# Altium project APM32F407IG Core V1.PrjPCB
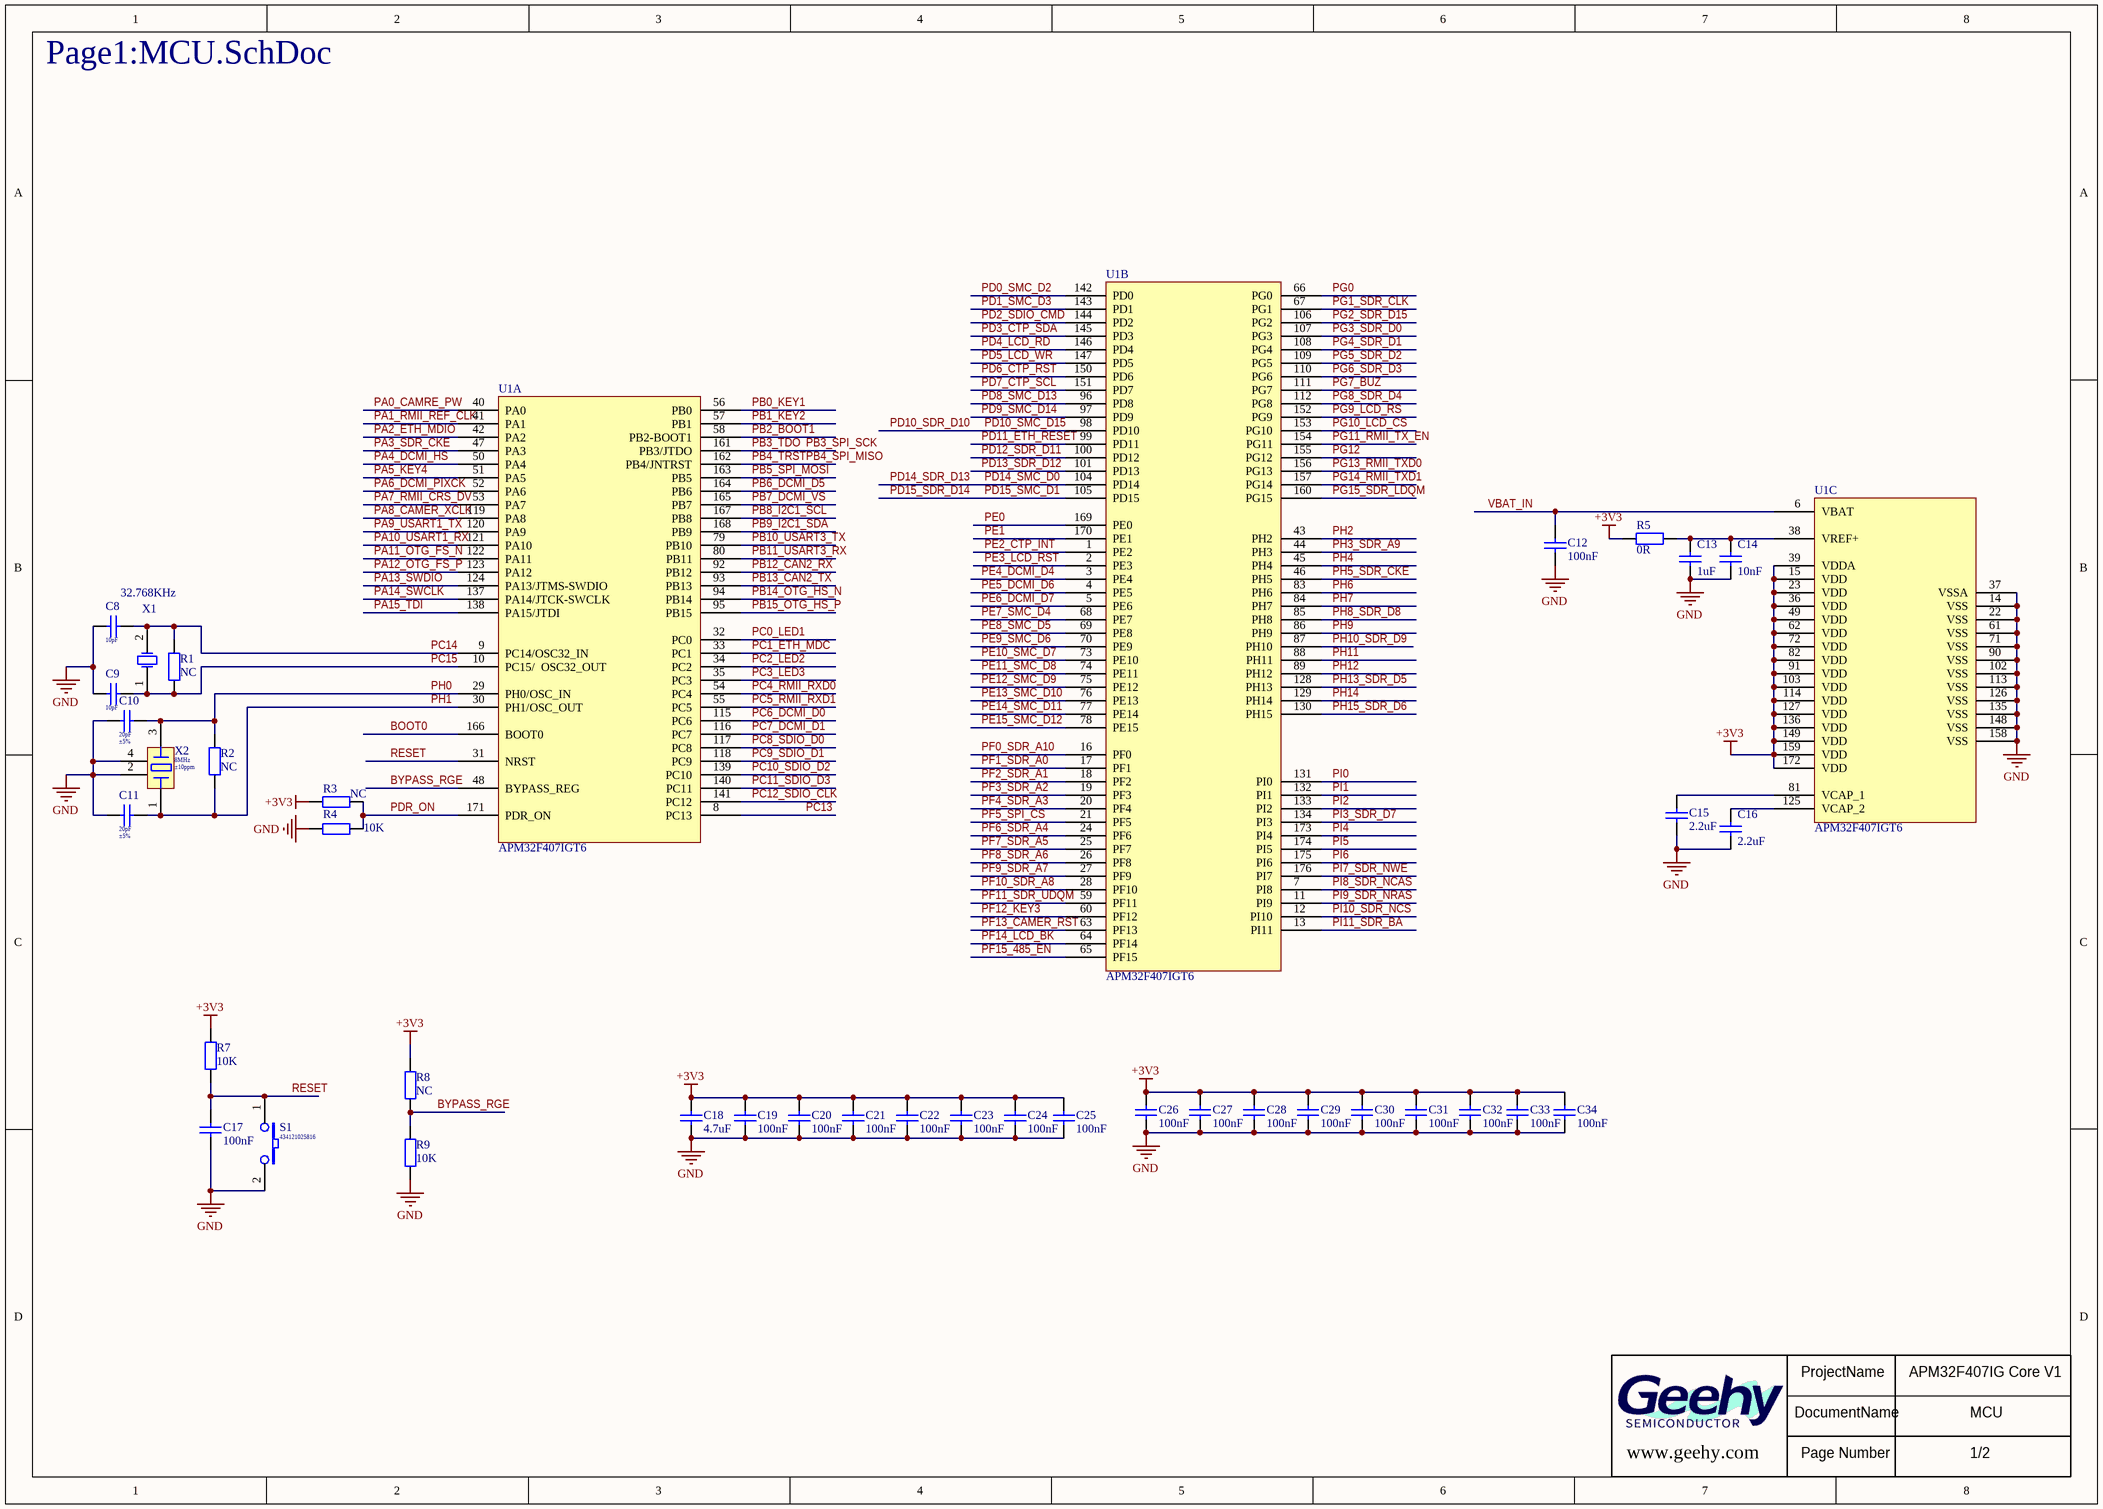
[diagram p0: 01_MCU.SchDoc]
2 sheets, 55 parts. Net scope: global (net labels, ports and power ports of the same name join across sheets).
Board file: APM32F407IG Core V1.PcbDoc
Sheets:
  01_MCU.SchDoc
  02_Connect.SchDoc

## Sheet 01_MCU.SchDoc
size A3

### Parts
C8  10pF  [C0603]
C9  10pF  [C0603]
C10  Tolerance: ±5%  [C0603]  (hidden comment: 20pF)
C11  Tolerance: ±5%  [C0603]  (hidden comment: 20pF)
C12  100nF  [C0603]
C13  1uF  [C0603]
C14  10nF  [C0603]
C15  2.2uF  [C0603]
C16  2.2uF  [C0603]
C17  100nF  [C0603]
C18  4.7uF  [C0805]
C19  100nF  [C0603]
C20  100nF  [C0603]
C21  100nF  [C0603]
C22  100nF  [C0603]
C23  100nF  [C0603]
C24  100nF  [C0603]
C25  100nF  [C0603]
C26  100nF  [C0603]
C27  100nF  [C0603]
C28  100nF  [C0603]
C29  100nF  [C0603]
C30  100nF  [C0603]
C31  100nF  [C0603]
C32  100nF  [C0603]
C33  100nF  [C0603]
C34  100nF  [C0603]
R1  NC  [R0603]
R2  NC  [R0603]
R3  NC  [R0603]
R4  10K  [R0603]
R5  0R  [R0603]
R7  10K  [R0603]
R8  NC  [R0603]
R9  10K  [R0603]
S1  434121025816  [SW-SMD-6X3R8X2R5-1]
U1  APM32F407IGT6  [LQFP-176N]  (parts A,B,C of 3)
X1  32.768KHz  [R1206]
X2  Tolerance: ±10ppm  [XTAL3225]  (hidden comment: 8MHz)

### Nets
+3V3: C18.1 C19.1 C20.1 C21.1 C22.1 C23.1 C24.1 C25.1 C26.1 C27.1 C28.1 C29.1 C30.1 C31.1 C32.1 C33.1 C34.1 R3.2 R5.1 R7.2 R8.2 U1.15(VDD) U1.23(VDD) U1.36(VDD) U1.39(VDDA) U1.49(VDD) U1.62(VDD) U1.72(VDD) U1.82(VDD) U1.91(VDD) U1.103(VDD) U1.114(VDD) U1.127(VDD) U1.136(VDD) U1.149(VDD) U1.159(VDD) U1.172(VDD)
GND: C8.2 C9.2 C10.2 C11.2 C12.2 C13.2 C14.2 C15.2 C16.2 C17.2 C18.2 C19.2 C20.2 C21.2 C22.2 C23.2 C24.2 C25.2 C26.2 C27.2 C28.2 C29.2 C30.2 C31.2 C32.2 C33.2 C34.2 R4.1 R9.1 S1.2 U1.14(VSS) U1.22(VSS) U1.37(VSSA) U1.61(VSS) U1.71(VSS) U1.90(VSS) U1.102(VSS) U1.113(VSS) U1.126(VSS) U1.135(VSS) U1.148(VSS) U1.158(VSS) X2.2(GND) X2.4(GND)
BOOT0: U1.166(BOOT0)
BYPASS_RGE: R8.1 R9.2 U1.48(BYPASS_REG)
PA0_CAMRE_PW: U1.40(PA0)
PA1_RMII_REF_CLK: U1.41(PA1)
PA2_ETH_MDIO: U1.42(PA2)
PA3_SDR_CKE: U1.47(PA3)
PA4_DCMI_HS: U1.50(PA4)
PA5_KEY4: U1.51(PA5)
PA6_DCMI_PIXCK: U1.52(PA6)
PA7_RMII_CRS_DV: U1.53(PA7)
PA8_CAMER_XCLK: U1.119(PA8)
PA9_USART1_TX: U1.120(PA9)
PA10_USART1_RX: U1.121(PA10)
PA11_OTG_FS_N: U1.122(PA11)
PA12_OTG_FS_P: U1.123(PA12)
PA13_SWDIO: U1.124(PA13/JTMS-SWDIO)
PA14_SWCLK: U1.137(PA14/JTCK-SWCLK)
PA15_TDI: U1.138(PA15/JTDI)
PB0_KEY1: U1.56(PB0)
PB1_KEY2: U1.57(PB1)
PB2_BOOT1: U1.58(PB2-BOOT1)
PB3_SPI_SCK: U1.161(PB3/JTDO)  [also labelled PB3_TDO]
PB4_SPI_MISO: U1.162(PB4/JNTRST)  [also labelled PB4_TRST]
PB5_SPI_MOSI: U1.163(PB5)
PB6_DCMI_D5: U1.164(PB6)
PB7_DCMI_VS: U1.165(PB7)
PB8_I2C1_SCL: U1.167(PB8)
PB9_I2C1_SDA: U1.168(PB9)
PB10_USART3_TX: U1.79(PB10)
PB11_USART3_RX: U1.80(PB11)
PB12_CAN2_RX: U1.92(PB12)
PB13_CAN2_TX: U1.93(PB13)
PB14_OTG_HS_N: U1.94(PB14)
PB15_OTG_HS_P: U1.95(PB15)
PC0_LED1: U1.32(PC0)
PC1_ETH_MDC: U1.33(PC1)
PC2_LED2: U1.34(PC2)
PC3_LED3: U1.35(PC3)
PC4_RMII_RXD0: U1.54(PC4)
PC5_RMII_RXD1: U1.55(PC5)
PC6_DCMI_D0: U1.115(PC6)
PC7_DCMI_D1: U1.116(PC7)
PC8_SDIO_D0: U1.117(PC8)
PC9_SDIO_D1: U1.118(PC9)
PC10_SDIO_D2: U1.139(PC10)
PC11_SDIO_D3: U1.140(PC11)
PC12_SDIO_CLK: U1.141(PC12)
PC13: U1.8(PC13)
PC14: C8.1 R1.2 U1.9(PC14/OSC32_IN) X1.2(OSC2)
PC15: C9.1 R1.1 U1.10(PC15/__OSC32_OUT) X1.1(OSC1)
PD0_SMC_D2: U1.142(PD0)
PD1_SMC_D3: U1.143(PD1)
PD2_SDIO_CMD: U1.144(PD2)
PD3_CTP_SDA: U1.145(PD3)
PD4_LCD_RD: U1.146(PD4)
PD5_LCD_WR: U1.147(PD5)
PD6_CTP_RST: U1.150(PD6)
PD7_CTP_SCL: U1.151(PD7)
PD8_SMC_D13: U1.96(PD8)
PD9_SMC_D14: U1.97(PD9)
PD10_SDR_D10: U1.98(PD10)  [also labelled PD10_SMC_D15]
PD11_ETH_RESET: U1.99(PD11)
PD12_SDR_D11: U1.100(PD12)
PD13_SDR_D12: U1.101(PD13)
PD14_SDR_D13: U1.104(PD14)  [also labelled PD14_SMC_D0]
PD15_SDR_D14: U1.105(PD15)  [also labelled PD15_SMC_D1]
PDR_ON: R3.1 R4.2 U1.171(PDR_ON)
PE0: U1.169(PE0)
PE1: U1.170(PE1)
PE2_CTP_INT: U1.1(PE2)
PE3_LCD_RST: U1.2(PE3)
PE4_DCMI_D4: U1.3(PE4)
PE5_DCMI_D6: U1.4(PE5)
PE6_DCMI_D7: U1.5(PE6)
PE7_SMC_D4: U1.68(PE7)
PE8_SMC_D5: U1.69(PE8)
PE9_SMC_D6: U1.70(PE9)
PE10_SMC_D7: U1.73(PE10)
PE11_SMC_D8: U1.74(PE11)
PE12_SMC_D9: U1.75(PE12)
PE13_SMC_D10: U1.76(PE13)
PE14_SMC_D11: U1.77(PE14)
PE15_SMC_D12: U1.78(PE15)
PF0_SDR_A10: U1.16(PF0)
PF1_SDR_A0: U1.17(PF1)
PF2_SDR_A1: U1.18(PF2)
PF3_SDR_A2: U1.19(PF3)
PF4_SDR_A3: U1.20(PF4)
PF5_SPI_CS: U1.21(PF5)
PF6_SDR_A4: U1.24(PF6)
PF7_SDR_A5: U1.25(PF7)
PF8_SDR_A6: U1.26(PF8)
PF9_SDR_A7: U1.27(PF9)
PF10_SDR_A8: U1.28(PF10)
PF11_SDR_UDQM: U1.59(PF11)
PF12_KEY3: U1.60(PF12)
PF13_CAMER_RST: U1.63(PF13)
PF14_LCD_BK: U1.64(PF14)
PF15_485_EN: U1.65(PF15)
PG0: U1.66(PG0)
PG1_SDR_CLK: U1.67(PG1)
PG2_SDR_D15: U1.106(PG2)
PG3_SDR_D0: U1.107(PG3)
PG4_SDR_D1: U1.108(PG4)
PG5_SDR_D2: U1.109(PG5)
PG6_SDR_D3: U1.110(PG6)
PG7_BUZ: U1.111(PG7)
PG8_SDR_D4: U1.112(PG8)
PG9_LCD_RS: U1.152(PG9)
PG10_LCD_CS: U1.153(PG10)
PG11_RMII_TX_EN: U1.154(PG11)
PG12: U1.155(PG12)
PG13_RMII_TXD0: U1.156(PG13)
PG14_RMII_TXD1: U1.157(PG14)
PG15_SDR_LDQM: U1.160(PG15)
PH0: C10.1 R2.2 U1.29(PH0/OSC_IN) X2.3
PH1: C11.1 R2.1 U1.30(PH1/OSC_OUT) X2.1
PH2: U1.43(PH2)
PH3_SDR_A9: U1.44(PH3)
PH4: U1.45(PH4)
PH5_SDR_CKE: U1.46(PH5)
PH6: U1.83(PH6)
PH7: U1.84(PH7)
PH8_SDR_D8: U1.85(PH8)
PH9: U1.86(PH9)
PH10_SDR_D9: U1.87(PH10)
PH11: U1.88(PH11)
PH12: U1.89(PH12)
PH13_SDR_D5: U1.128(PH13)
PH14: U1.129(PH14)
PH15_SDR_D6: U1.130(PH15)
PI0: U1.131(PI0)
PI1: U1.132(PI1)
PI2: U1.133(PI2)
PI3_SDR_D7: U1.134(PI3)
PI4: U1.173(PI4)
PI5: U1.174(PI5)
PI6: U1.175(PI6)
PI7_SDR_NWE: U1.176(PI7)
PI8_SDR_NCAS: U1.7(PI8)
PI9_SDR_NRAS: U1.11(PI9)
PI10_SDR_NCS: U1.12(PI10)
PI11_SDR_BA: U1.13(PI11)
RESET: C17.1 R7.1 S1.1 U1.31(NRST)
VBAT_IN: C12.1 U1.6(VBAT)
NetC13_1: C13.1 C14.1 R5.2 U1.38(VREF+)
NetC15_1: C15.1 U1.81(VCAP_1)
NetC16_1: C16.1 U1.125(VCAP_2)

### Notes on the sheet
- Page1:MCU.SchDoc
- ProjectName
- APM32F407IG Core V1
- www.geehy.com
- DocumentName
- Page Number
- 1/2
- MCU

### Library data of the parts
C8 C9 = 101CC-00365BE.01: SMD,电容量10pF,额定电压50V,偏差±1pF,材质C0G,0603; Allow Altenative Part: Y; Tolerance: ±1pF; Rated Voltage: 50V; Temperature Coefficient: C0G; serial number: 13; Categories: 电容; COMPONENTLINK 1 DESCRIPTION: GetDatasheet; Modify time: 2015年07月10号; Approved: YES
C10 C11 = 101CC-00471BW.01: 安装方式SMD,电容量20pF,额定电压50V,偏差±5%,材质NPO,0603; Allow Altenative Part: Y; Rated Voltage: 50V; Temperature Coefficient: NP0; serial number: 38; Categories: 电容; COMPONENTLINK 1 DESCRIPTION: GetDatasheet; Modify time: 2016年08月22号; Approved: YES
C12 C17 C19-C34 = 101CC-00003IA.01: SMD,电容量100nF,额定电压50V,偏差±10%,材质X7R,0603; Allow Altenative Part: Y; serial number: 12; Categories: 电容; Tolerance: ±10%; Rated Voltage: 50V; Temperature Coefficient: X7R; COMPONENTLINK 1 DESCRIPTION: OpenDatasheet; Modify time: 2018年10月27号; Preferred: P
C13 = 101CC-00005IA.01: SMD,电容量1uF,额定电压50V,偏差±10%,材质X5R,0603; Allow Altenative Part: Y; serial number: 14; Categories: 电容; Tolerance: ±10%; Rated Voltage: 50V; Temperature Coefficient: X5R; COMPONENTLINK 1 DESCRIPTION: OpenDatasheet; Modify time: 2018年10月27号; Preferred: P
C14 = 101CC-00002IA.01: SMD,电容量10nF,额定电压50V,偏差±10%,材质X7R,0603; Allow Altenative Part: Y; serial number: 11; Categories: 电容; Tolerance: ±10%; Rated Voltage: 50V; Temperature Coefficient: X7R; COMPONENTLINK 1 DESCRIPTION: OpenDatasheet; Modify time: 2018年10月27号; Preferred: P
C15 C16 = 101CC-00009IA.01: SMD,电容量2.2uF,额定电压25V,偏差±10%,材质X5R,0603; Allow Altenative Part: Y; serial number: 16; Categories: 电容; Tolerance: ±10%; Rated Voltage: 25V; Temperature Coefficient: X5R; COMPONENTLINK 1 DESCRIPTION: OpenDatasheet; Modify time: 2018年10月27号; Preferred: P
C18 = 101CC-00357OD.01: SMD,电容量4.7uF,额定电压50V,精度±10%,材质X5R,0805; Allow Altenative Part: Y; serial number: 57; Categories: 电容; Tolerance: ±10%; Rated Voltage: 50V; Temperature Coefficient: X5R; COMPONENTLINK 1 DESCRIPTION: GetDatasheet; Modify time: 2017年01月07号; Approved: YES
R1-R3 R8 = 101RC-00012IA.01: SMD,阻值0R,精度±1%,0603,额定功率1/10W; Allow Altenative Part: Y; serial number: 160; Categories: 电阻; Value: 0R; Tolerance: ±1%; Rated Power: 1/10W; COMPONENTLINK 1 DESCRIPTION: OpenDatasheet; Modify time: 2018年10月29号; Preferred: P
R4 R7 R9 = 101RC-00003IA.01: SMD,阻值10K,精度±1%,0603,额定功率1/10W; Allow Altenative Part: Y; serial number: 153; Categories: 电阻; Tolerance: ±1%; Rated Power: 1/10W; COMPONENTLINK 1 DESCRIPTION: OpenDatasheet; Modify time: 2018年10月29号; Preferred: P
R5 = 101RC-00012IA.01: SMD,阻值0R,精度±1%,0603,额定功率1/10W; Allow Altenative Part: Y; serial number: 160; Categories: 电阻; Tolerance: ±1%; Rated Power: 1/10W; COMPONENTLINK 1 DESCRIPTION: OpenDatasheet; Modify time: 2018年10月29号; Preferred: P
S1 = 101SA-00035BV.01: 安装方式SMD,封装尺寸6.00x3.80x2.50mm,2PIN,装配角度180度,黑色; Allow Altenative Part: Y; serial number: 17; Categories: 开关; COMPONENTLINK 1 DESCRIPTION: OpenDatasheet; Modify time: 2019年8月10号
X1 = XTAL: Crystal Oscillator
X2 = 101XB-00001AN.01: SMD,材质陶瓷外壳,封装外壳3225,精度±10ppm,震荡频率8MHz; Allow Altenative Part: Y; serial number: 1; Categories: 晶振; COMPONENTLINK 1 DESCRIPTION: OpenDatasheet; Remark: Verified by BU1（吴明徽）check list V1.0; Modify time: 2015年12月2号; Approved: YES

## Sheet 02_Connect.SchDoc
size A3
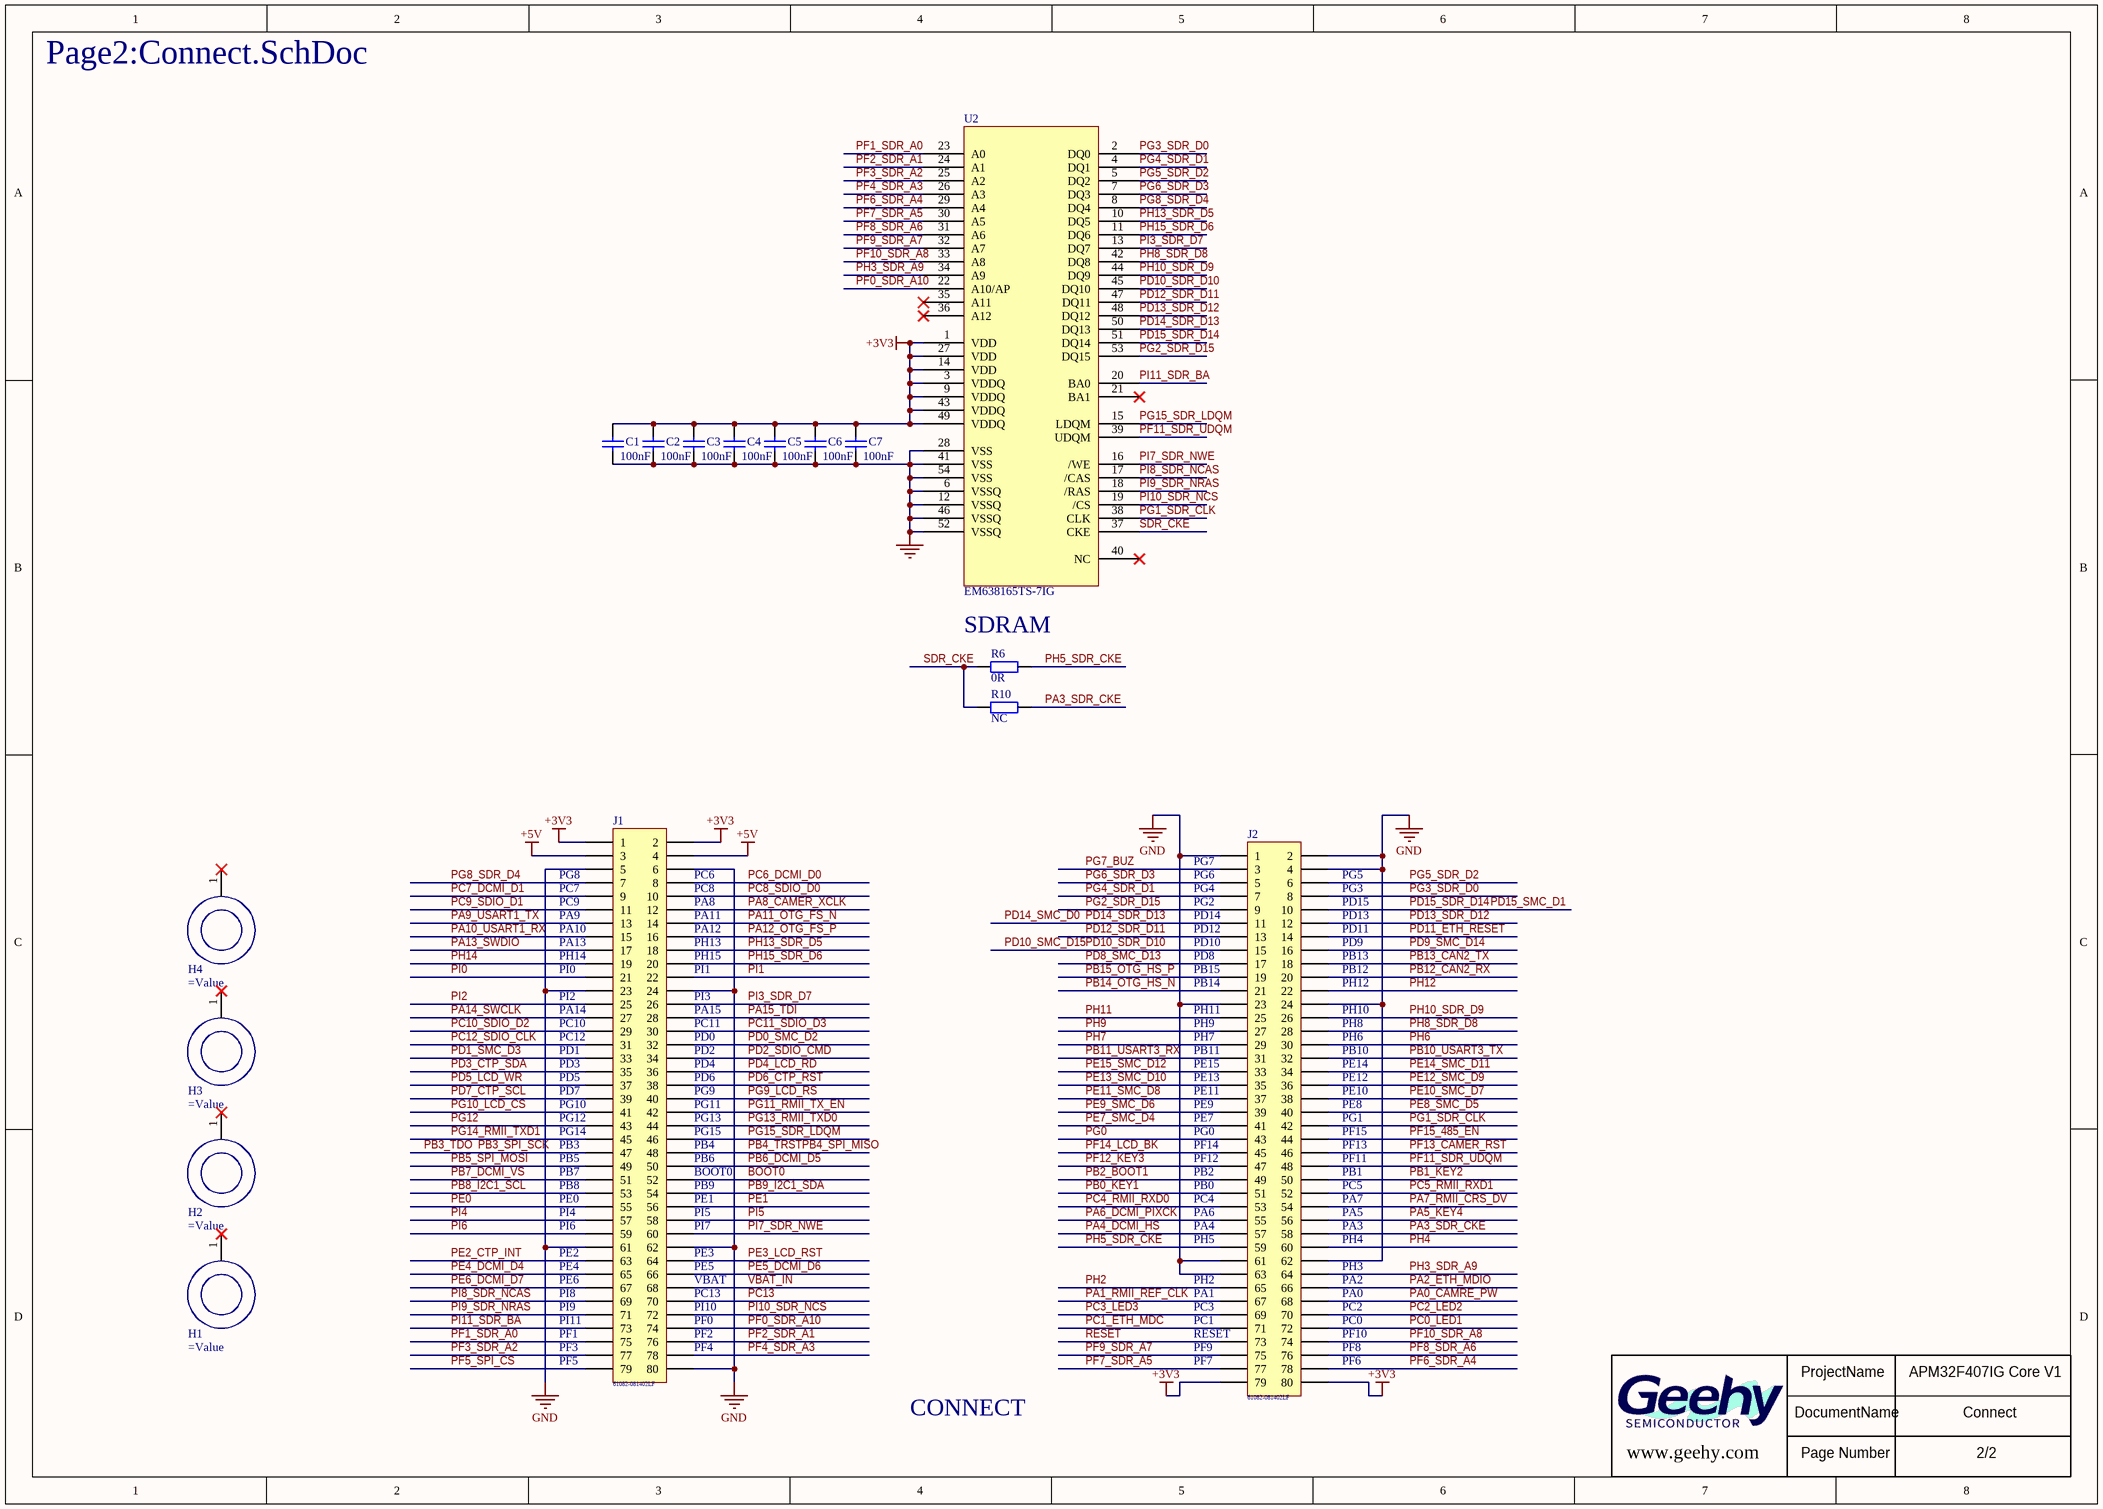
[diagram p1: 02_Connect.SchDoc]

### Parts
C1  100nF  [C0603]
C2  100nF  [C0603]
C3  100nF  [C0603]
C4  100nF  [C0603]
C5  100nF  [C0603]
C6  100nF  [C0603]
C7  100nF  [C0603]
H1  (no value)  [THC5R5D3R4-M3-PTH]
H2  (no value)  [THC5R5D3R4-M3-PTH]
H3  (no value)  [THC5R5D3R4-M3-PTH]
H4  (no value)  [THC5R5D3R4-M3-PTH]
J1  61082-081402LF  [B2B2X40R-0R8-SM-Z-H3R7]
J2  61082-081402LF  [B2B2X40R-0R8-SM-Z-H3R7]
R6  0R  [R0603]
R10  NC  [R0603]
U2  EM638165TS-7IG  [TSOP54]

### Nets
+3V3: C1.1 C2.1 C3.1 C4.1 C5.1 C6.1 C7.1 J1.1 J1.2 J2.79 J2.80 U2.1(VDD) U2.3(VDDQ) U2.9(VDDQ) U2.14(VDD) U2.27(VDD) U2.43(VDDQ) U2.49(VDDQ)
+5V: J1.3 J1.4
GND: C1.2 C2.2 C3.2 C4.2 C5.2 C6.2 C7.2 J1.5 J1.6 J1.23 J1.24 J1.61 J1.62 J1.80 J2.1 J2.2 J2.4 J2.23 J2.24 J2.61 J2.62 J2.63 U2.6(VSSQ) U2.12(VSSQ) U2.28(VSS) U2.41(VSS) U2.46(VSSQ) U2.52(VSSQ) U2.54(VSS)
BOOT0: J1.52
PA0_CAMRE_PW: J2.68
PA1_RMII_REF_CLK: J2.67
PA2_ETH_MDIO: J2.66
PA3_SDR_CKE: J2.58 R10.2
PA4_DCMI_HS: J2.57
PA5_KEY4: J2.56
PA6_DCMI_PIXCK: J2.55
PA7_RMII_CRS_DV: J2.54
PA8_CAMER_XCLK: J1.12
PA9_USART1_TX: J1.13
PA10_USART1_RX: J1.15
PA11_OTG_FS_N: J1.14
PA12_OTG_FS_P: J1.16
PA13_SWDIO: J1.17
PA14_SWCLK: J1.27
PA15_TDI: J1.28
PB0_KEY1: J2.51
PB1_KEY2: J2.50
PB2_BOOT1: J2.49
PB3_SPI_SCK: J1.47  [also labelled PB3_TDO]
PB4_SPI_MISO: J1.48  [also labelled PB4_TRST]
PB5_SPI_MOSI: J1.49
PB6_DCMI_D5: J1.50
PB7_DCMI_VS: J1.51
PB8_I2C1_SCL: J1.53
PB9_I2C1_SDA: J1.54
PB10_USART3_TX: J2.32
PB11_USART3_RX: J2.31
PB12_CAN2_RX: J2.20
PB13_CAN2_TX: J2.18
PB14_OTG_HS_N: J2.21
PB15_OTG_HS_P: J2.19
PC0_LED1: J2.72
PC1_ETH_MDC: J2.71
PC2_LED2: J2.70
PC3_LED3: J2.69
PC4_RMII_RXD0: J2.53
PC5_RMII_RXD1: J2.52
PC6_DCMI_D0: J1.8
PC7_DCMI_D1: J1.9
PC8_SDIO_D0: J1.10
PC9_SDIO_D1: J1.11
PC10_SDIO_D2: J1.29
PC11_SDIO_D3: J1.30
PC12_SDIO_CLK: J1.31
PC13: J1.70
PD0_SMC_D2: J1.32
PD1_SMC_D3: J1.33
PD2_SDIO_CMD: J1.34
PD3_CTP_SDA: J1.35
PD4_LCD_RD: J1.36
PD5_LCD_WR: J1.37
PD6_CTP_RST: J1.38
PD7_CTP_SCL: J1.39
PD8_SMC_D13: J2.17
PD9_SMC_D14: J2.16
PD10_SDR_D10: J2.15 U2.45(DQ10)  [also labelled PD10_SMC_D15]
PD11_ETH_RESET: J2.14
PD12_SDR_D11: J2.13 U2.47(DQ11)
PD13_SDR_D12: J2.12 U2.48(DQ12)
PD14_SDR_D13: J2.11 U2.50(DQ13)  [also labelled PD14_SMC_D0]
PD15_SDR_D14: J2.10 U2.51(DQ14)  [also labelled PD15_SMC_D1]
PE0: J1.55
PE1: J1.56
PE2_CTP_INT: J1.63
PE3_LCD_RST: J1.64
PE4_DCMI_D4: J1.65
PE5_DCMI_D6: J1.66
PE6_DCMI_D7: J1.67
PE7_SMC_D4: J2.41
PE8_SMC_D5: J2.40
PE9_SMC_D6: J2.39
PE10_SMC_D7: J2.38
PE11_SMC_D8: J2.37
PE12_SMC_D9: J2.36
PE13_SMC_D10: J2.35
PE14_SMC_D11: J2.34
PE15_SMC_D12: J2.33
PF0_SDR_A10: J1.74 U2.22(A10/AP)
PF1_SDR_A0: J1.75 U2.23(A0)
PF2_SDR_A1: J1.76 U2.24(A1)
PF3_SDR_A2: J1.77 U2.25(A2)
PF4_SDR_A3: J1.78 U2.26(A3)
PF5_SPI_CS: J1.79
PF6_SDR_A4: J2.78 U2.29(A4)
PF7_SDR_A5: J2.77 U2.30(A5)
PF8_SDR_A6: J2.76 U2.31(A6)
PF9_SDR_A7: J2.75 U2.32(A7)
PF10_SDR_A8: J2.74 U2.33(A8)
PF11_SDR_UDQM: J2.48 U2.39(UDQM)
PF12_KEY3: J2.47
PF13_CAMER_RST: J2.46
PF14_LCD_BK: J2.45
PF15_485_EN: J2.44
PG0: J2.43
PG1_SDR_CLK: J2.42 U2.38(CLK)
PG2_SDR_D15: J2.9 U2.53(DQ15)
PG3_SDR_D0: J2.8 U2.2(DQ0)
PG4_SDR_D1: J2.7 U2.4(DQ1)
PG5_SDR_D2: J2.6 U2.5(DQ2)
PG6_SDR_D3: J2.5 U2.7(DQ3)
PG7_BUZ: J2.3
PG8_SDR_D4: J1.7 U2.8(DQ4)
PG9_LCD_RS: J1.40
PG10_LCD_CS: J1.41
PG11_RMII_TX_EN: J1.42
PG12: J1.43
PG13_RMII_TXD0: J1.44
PG14_RMII_TXD1: J1.45
PG15_SDR_LDQM: J1.46 U2.15(LDQM)
PH2: J2.65
PH3_SDR_A9: J2.64 U2.34(A9)
PH4: J2.60
PH5_SDR_CKE: J2.59 R6.2
PH6: J2.30
PH7: J2.29
PH8_SDR_D8: J2.28 U2.42(DQ8)
PH9: J2.27
PH10_SDR_D9: J2.26 U2.44(DQ9)
PH11: J2.25
PH12: J2.22
PH13_SDR_D5: J1.18 U2.10(DQ5)
PH14: J1.19
PH15_SDR_D6: J1.20 U2.11(DQ6)
PI0: J1.21
PI1: J1.22
PI2: J1.25
PI3_SDR_D7: J1.26 U2.13(DQ7)
PI4: J1.57
PI5: J1.58
PI6: J1.59
PI7_SDR_NWE: J1.60 U2.16(/WE)
PI8_SDR_NCAS: J1.69 U2.17(/CAS)
PI9_SDR_NRAS: J1.71 U2.18(/RAS)
PI10_SDR_NCS: J1.72 U2.19(/CS)
PI11_SDR_BA: J1.73 U2.20(BA0)
RESET: J2.73
SDR_CKE: R6.1 R10.1 U2.37(CKE)
VBAT_IN: J1.68

Not connected (* = marked no-connect by the designer): H1 1*; H2 1*; H3 1*; H4 1*; U2 21(BA1)* 35(A11)* 36(A12)* 40(NC)*

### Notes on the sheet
- Page2:Connect.SchDoc
- (near R6) SDRAM
- (near J1) PA9
- (near J1) PC9
- (near J1) PC7
- (near J1) PG8
- (near J1) PA11
- (near J1) PA8
- (near J1) PC8
- (near J1) PC6
- (near J2) PG7
- (near J2) PD14
- (near J2) PG2
- (near J2) PG4
- (near J2) PG6
- (near J2) PD13
- (near J2) PD15
- (near J2) PG3
- (near J2) PG5
- (near J1) PI0
- (near J1) PH14
- (near J1) PA13
- (near J1) PA10
- (near J1) PI1
- (near J1) PH15
- (near J1) PH13
- (near J1) PA12
- (near J2) PB14
- (near J2) PB15
- (near J2) PD8
- (near J2) PD10
- (near J2) PD12
- (near J2) PH12
- (near J2) PB12
- (near J2) PB13
- (near J2) PD9
- (near J2) PD11
- (near J1) PD1
- (near J1) PC12
- (near J1) PC10
- (near J1) PA14
- (near J1) PI2
- (near J1) PD2
- (near J1) PD0
- (near J1) PC11
- (near J1) PA15
- (near J1) PI3
- (near J2) PB11
- (near J2) PH7
- (near J2) PH9
- (near J2) PH11
- (near J2) PB10
- (near J2) PH6
- (near J2) PH8
- (near J2) PH10
- (near J1) PG12
- (near J1) PG10
- (near J1) PD7
- (near J1) PD5
- (near J1) PD3
- (near J1) PG13
- (near J1) PG11
- (near J1) PG9
- (near J1) PD6
- (near J1) PD4
- (near J2) PE7
- (near J2) PE9
- (near J2) PE11
- (near J2) PE13
- (near J2) PE15
- (near J2) PG1
- (near J2) PE8
- (near J2) PE10
- (near J2) PE12
- (near J2) PE14
- (near J1) PB8
- (near J1) PB7
- (near J1) PB5
- (near J1) PB3
- (near J1) PG14
- (near J1) PB9
- (near J1) BOOT0
- (near J1) PB6
- (near J1) PB4
- (near J1) PG15
- (near J2) PB0
- (near J2) PB2
- (near J2) PF12
- (near J2) PF14
- (near J2) PG0
- (near J2) PC5
- (near J2) PB1
- (near J2) PF11
- (near J2) PF13
- (near J2) PF15
- (near J1) PE2
- (near J1) PI6
- (near J1) PI4
- (near J1) PE0
- (near J1) PE3
- (near J1) PI7
- (near J1) PI5
- (near J1) PE1
- (near J2) PH5
- (near J2) PA4
- (near J2) PA6
- (near J2) PC4
- (near J2) PH4
- (near J2) PA3
- (near J2) PA5
- (near J2) PA7
- (near J1) PI11
- (near J1) PI9
- (near J1) PI8
- (near J1) PE6
- (near J1) PE4
- (near J1) PF0
- (near J1) PI10
- (near J1) PC13
- (near J1) VBAT
- (near J1) PE5
- (near J2) PC1
- (near J2) PC3
- (near J2) PA1
- (near J2) PH2
- (near J2) PC0
- (near J2) PC2
- (near J2) PA0
- (near J2) PA2
- (near J2) PH3
- (near J1) PF5
- (near J1) PF3
- (near J1) PF1
- (near J1) PF4
- (near J1) PF2
- (near J2) PF7
- (near J2) PF9
- (near J2) RESET
- (near J2) PF6
- (near J2) PF8
- (near J2) PF10
- ProjectName
- APM32F407IG Core V1
- CONNECT
- www.geehy.com
- DocumentName
- Page Number
- Connect
- 2/2

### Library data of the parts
C1-C7 = 101CC-00003IA.01: as C12 on sheet 01_MCU
H1-H4 = M3-PTH: Part Number: M3-PTH; Allow Altenative Part: Y; serial number: 15; Categories: 符号; Modify time: 2017年2月13日; Approved: YES
J1 J2 = 101NH-00010CO.01: SMD,座子,封装脚距0.80mm,180度,引脚数目2x40PIN,塑高/针长3.7mm/无,白色; Allow Altenative Part: Y; serial number: 304; Categories: 连接器; COMPONENTLINK 1 DESCRIPTION: GetDatasheet; Modify time: 2017年09月11号; Approved: YES
R6 = 101RC-00012IA.01: as R5 on sheet 01_MCU
R10 = 101RC-00012IA.01: as R1 on sheet 01_MCU

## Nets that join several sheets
+3V3: 01_MCU (37 pins), 02_Connect (18 pins)
GND: 01_MCU (44 pins), 02_Connect (29 pins)
BOOT0: 01_MCU (U1.166), 02_Connect (J1.52)
PA0_CAMRE_PW: 01_MCU (U1.40), 02_Connect (J2.68)
PA1_RMII_REF_CLK: 01_MCU (U1.41), 02_Connect (J2.67)
PA2_ETH_MDIO: 01_MCU (U1.42), 02_Connect (J2.66)
PA3_SDR_CKE: 01_MCU (U1.47), 02_Connect (J2.58 R10.2)
PA4_DCMI_HS: 01_MCU (U1.50), 02_Connect (J2.57)
PA5_KEY4: 01_MCU (U1.51), 02_Connect (J2.56)
PA6_DCMI_PIXCK: 01_MCU (U1.52), 02_Connect (J2.55)
PA7_RMII_CRS_DV: 01_MCU (U1.53), 02_Connect (J2.54)
PA8_CAMER_XCLK: 01_MCU (U1.119), 02_Connect (J1.12)
PA9_USART1_TX: 01_MCU (U1.120), 02_Connect (J1.13)
PA10_USART1_RX: 01_MCU (U1.121), 02_Connect (J1.15)
PA11_OTG_FS_N: 01_MCU (U1.122), 02_Connect (J1.14)
PA12_OTG_FS_P: 01_MCU (U1.123), 02_Connect (J1.16)
PA13_SWDIO: 01_MCU (U1.124), 02_Connect (J1.17)
PA14_SWCLK: 01_MCU (U1.137), 02_Connect (J1.27)
PA15_TDI: 01_MCU (U1.138), 02_Connect (J1.28)
PB0_KEY1: 01_MCU (U1.56), 02_Connect (J2.51)
PB1_KEY2: 01_MCU (U1.57), 02_Connect (J2.50)
PB2_BOOT1: 01_MCU (U1.58), 02_Connect (J2.49)
PB3_SPI_SCK: 01_MCU (U1.161), 02_Connect (J1.47)
PB4_SPI_MISO: 01_MCU (U1.162), 02_Connect (J1.48)
PB5_SPI_MOSI: 01_MCU (U1.163), 02_Connect (J1.49)
PB6_DCMI_D5: 01_MCU (U1.164), 02_Connect (J1.50)
PB7_DCMI_VS: 01_MCU (U1.165), 02_Connect (J1.51)
PB8_I2C1_SCL: 01_MCU (U1.167), 02_Connect (J1.53)
PB9_I2C1_SDA: 01_MCU (U1.168), 02_Connect (J1.54)
PB10_USART3_TX: 01_MCU (U1.79), 02_Connect (J2.32)
PB11_USART3_RX: 01_MCU (U1.80), 02_Connect (J2.31)
PB12_CAN2_RX: 01_MCU (U1.92), 02_Connect (J2.20)
PB13_CAN2_TX: 01_MCU (U1.93), 02_Connect (J2.18)
PB14_OTG_HS_N: 01_MCU (U1.94), 02_Connect (J2.21)
PB15_OTG_HS_P: 01_MCU (U1.95), 02_Connect (J2.19)
PC0_LED1: 01_MCU (U1.32), 02_Connect (J2.72)
PC1_ETH_MDC: 01_MCU (U1.33), 02_Connect (J2.71)
PC2_LED2: 01_MCU (U1.34), 02_Connect (J2.70)
PC3_LED3: 01_MCU (U1.35), 02_Connect (J2.69)
PC4_RMII_RXD0: 01_MCU (U1.54), 02_Connect (J2.53)
PC5_RMII_RXD1: 01_MCU (U1.55), 02_Connect (J2.52)
PC6_DCMI_D0: 01_MCU (U1.115), 02_Connect (J1.8)
PC7_DCMI_D1: 01_MCU (U1.116), 02_Connect (J1.9)
PC8_SDIO_D0: 01_MCU (U1.117), 02_Connect (J1.10)
PC9_SDIO_D1: 01_MCU (U1.118), 02_Connect (J1.11)
PC10_SDIO_D2: 01_MCU (U1.139), 02_Connect (J1.29)
PC11_SDIO_D3: 01_MCU (U1.140), 02_Connect (J1.30)
PC12_SDIO_CLK: 01_MCU (U1.141), 02_Connect (J1.31)
PC13: 01_MCU (U1.8), 02_Connect (J1.70)
PD0_SMC_D2: 01_MCU (U1.142), 02_Connect (J1.32)
PD1_SMC_D3: 01_MCU (U1.143), 02_Connect (J1.33)
PD2_SDIO_CMD: 01_MCU (U1.144), 02_Connect (J1.34)
PD3_CTP_SDA: 01_MCU (U1.145), 02_Connect (J1.35)
PD4_LCD_RD: 01_MCU (U1.146), 02_Connect (J1.36)
PD5_LCD_WR: 01_MCU (U1.147), 02_Connect (J1.37)
PD6_CTP_RST: 01_MCU (U1.150), 02_Connect (J1.38)
PD7_CTP_SCL: 01_MCU (U1.151), 02_Connect (J1.39)
PD8_SMC_D13: 01_MCU (U1.96), 02_Connect (J2.17)
PD9_SMC_D14: 01_MCU (U1.97), 02_Connect (J2.16)
PD10_SDR_D10: 01_MCU (U1.98), 02_Connect (J2.15 U2.45)
PD11_ETH_RESET: 01_MCU (U1.99), 02_Connect (J2.14)
PD12_SDR_D11: 01_MCU (U1.100), 02_Connect (J2.13 U2.47)
PD13_SDR_D12: 01_MCU (U1.101), 02_Connect (J2.12 U2.48)
PD14_SDR_D13: 01_MCU (U1.104), 02_Connect (J2.11 U2.50)
PD15_SDR_D14: 01_MCU (U1.105), 02_Connect (J2.10 U2.51)
PE0: 01_MCU (U1.169), 02_Connect (J1.55)
PE1: 01_MCU (U1.170), 02_Connect (J1.56)
PE2_CTP_INT: 01_MCU (U1.1), 02_Connect (J1.63)
PE3_LCD_RST: 01_MCU (U1.2), 02_Connect (J1.64)
PE4_DCMI_D4: 01_MCU (U1.3), 02_Connect (J1.65)
PE5_DCMI_D6: 01_MCU (U1.4), 02_Connect (J1.66)
PE6_DCMI_D7: 01_MCU (U1.5), 02_Connect (J1.67)
PE7_SMC_D4: 01_MCU (U1.68), 02_Connect (J2.41)
PE8_SMC_D5: 01_MCU (U1.69), 02_Connect (J2.40)
PE9_SMC_D6: 01_MCU (U1.70), 02_Connect (J2.39)
PE10_SMC_D7: 01_MCU (U1.73), 02_Connect (J2.38)
PE11_SMC_D8: 01_MCU (U1.74), 02_Connect (J2.37)
PE12_SMC_D9: 01_MCU (U1.75), 02_Connect (J2.36)
PE13_SMC_D10: 01_MCU (U1.76), 02_Connect (J2.35)
PE14_SMC_D11: 01_MCU (U1.77), 02_Connect (J2.34)
PE15_SMC_D12: 01_MCU (U1.78), 02_Connect (J2.33)
PF0_SDR_A10: 01_MCU (U1.16), 02_Connect (J1.74 U2.22)
PF1_SDR_A0: 01_MCU (U1.17), 02_Connect (J1.75 U2.23)
PF2_SDR_A1: 01_MCU (U1.18), 02_Connect (J1.76 U2.24)
PF3_SDR_A2: 01_MCU (U1.19), 02_Connect (J1.77 U2.25)
PF4_SDR_A3: 01_MCU (U1.20), 02_Connect (J1.78 U2.26)
PF5_SPI_CS: 01_MCU (U1.21), 02_Connect (J1.79)
PF6_SDR_A4: 01_MCU (U1.24), 02_Connect (J2.78 U2.29)
PF7_SDR_A5: 01_MCU (U1.25), 02_Connect (J2.77 U2.30)
PF8_SDR_A6: 01_MCU (U1.26), 02_Connect (J2.76 U2.31)
PF9_SDR_A7: 01_MCU (U1.27), 02_Connect (J2.75 U2.32)
PF10_SDR_A8: 01_MCU (U1.28), 02_Connect (J2.74 U2.33)
PF11_SDR_UDQM: 01_MCU (U1.59), 02_Connect (J2.48 U2.39)
PF12_KEY3: 01_MCU (U1.60), 02_Connect (J2.47)
PF13_CAMER_RST: 01_MCU (U1.63), 02_Connect (J2.46)
PF14_LCD_BK: 01_MCU (U1.64), 02_Connect (J2.45)
PF15_485_EN: 01_MCU (U1.65), 02_Connect (J2.44)
PG0: 01_MCU (U1.66), 02_Connect (J2.43)
PG1_SDR_CLK: 01_MCU (U1.67), 02_Connect (J2.42 U2.38)
PG2_SDR_D15: 01_MCU (U1.106), 02_Connect (J2.9 U2.53)
PG3_SDR_D0: 01_MCU (U1.107), 02_Connect (J2.8 U2.2)
PG4_SDR_D1: 01_MCU (U1.108), 02_Connect (J2.7 U2.4)
PG5_SDR_D2: 01_MCU (U1.109), 02_Connect (J2.6 U2.5)
PG6_SDR_D3: 01_MCU (U1.110), 02_Connect (J2.5 U2.7)
PG7_BUZ: 01_MCU (U1.111), 02_Connect (J2.3)
PG8_SDR_D4: 01_MCU (U1.112), 02_Connect (J1.7 U2.8)
PG9_LCD_RS: 01_MCU (U1.152), 02_Connect (J1.40)
PG10_LCD_CS: 01_MCU (U1.153), 02_Connect (J1.41)
PG11_RMII_TX_EN: 01_MCU (U1.154), 02_Connect (J1.42)
PG12: 01_MCU (U1.155), 02_Connect (J1.43)
PG13_RMII_TXD0: 01_MCU (U1.156), 02_Connect (J1.44)
PG14_RMII_TXD1: 01_MCU (U1.157), 02_Connect (J1.45)
PG15_SDR_LDQM: 01_MCU (U1.160), 02_Connect (J1.46 U2.15)
PH2: 01_MCU (U1.43), 02_Connect (J2.65)
PH3_SDR_A9: 01_MCU (U1.44), 02_Connect (J2.64 U2.34)
PH4: 01_MCU (U1.45), 02_Connect (J2.60)
PH5_SDR_CKE: 01_MCU (U1.46), 02_Connect (J2.59 R6.2)
PH6: 01_MCU (U1.83), 02_Connect (J2.30)
PH7: 01_MCU (U1.84), 02_Connect (J2.29)
PH8_SDR_D8: 01_MCU (U1.85), 02_Connect (J2.28 U2.42)
PH9: 01_MCU (U1.86), 02_Connect (J2.27)
PH10_SDR_D9: 01_MCU (U1.87), 02_Connect (J2.26 U2.44)
PH11: 01_MCU (U1.88), 02_Connect (J2.25)
PH12: 01_MCU (U1.89), 02_Connect (J2.22)
PH13_SDR_D5: 01_MCU (U1.128), 02_Connect (J1.18 U2.10)
PH14: 01_MCU (U1.129), 02_Connect (J1.19)
PH15_SDR_D6: 01_MCU (U1.130), 02_Connect (J1.20 U2.11)
PI0: 01_MCU (U1.131), 02_Connect (J1.21)
PI1: 01_MCU (U1.132), 02_Connect (J1.22)
PI2: 01_MCU (U1.133), 02_Connect (J1.25)
PI3_SDR_D7: 01_MCU (U1.134), 02_Connect (J1.26 U2.13)
PI4: 01_MCU (U1.173), 02_Connect (J1.57)
PI5: 01_MCU (U1.174), 02_Connect (J1.58)
PI6: 01_MCU (U1.175), 02_Connect (J1.59)
PI7_SDR_NWE: 01_MCU (U1.176), 02_Connect (J1.60 U2.16)
PI8_SDR_NCAS: 01_MCU (U1.7), 02_Connect (J1.69 U2.17)
PI9_SDR_NRAS: 01_MCU (U1.11), 02_Connect (J1.71 U2.18)
PI10_SDR_NCS: 01_MCU (U1.12), 02_Connect (J1.72 U2.19)
PI11_SDR_BA: 01_MCU (U1.13), 02_Connect (J1.73 U2.20)
RESET: 01_MCU (C17.1 R7.1 S1.1 U1.31), 02_Connect (J2.73)
VBAT_IN: 01_MCU (C12.1 U1.6), 02_Connect (J1.68)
